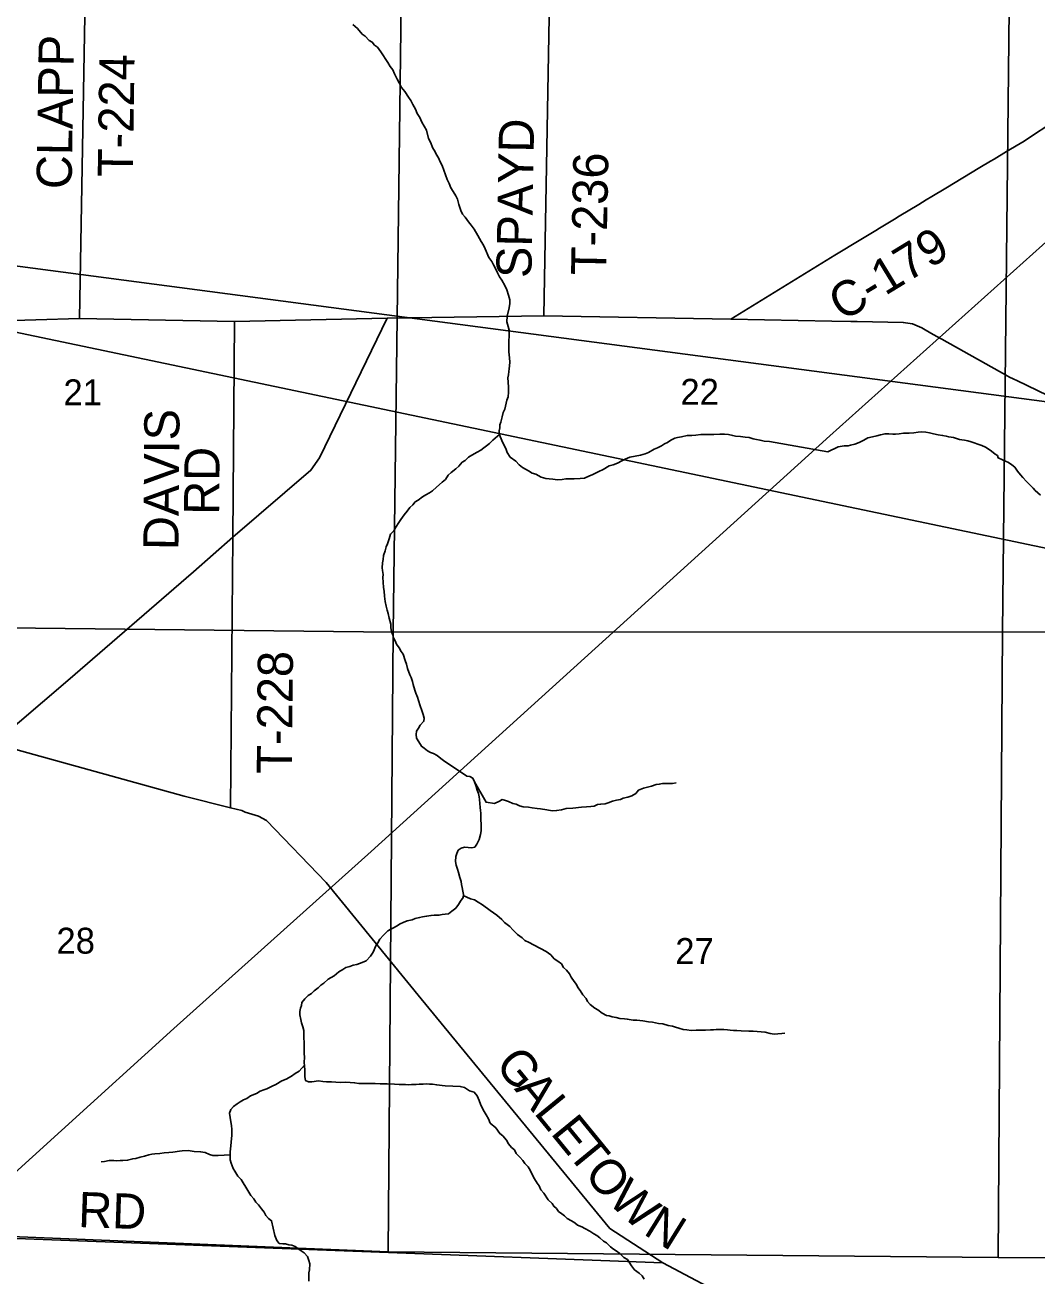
# Model space of a CAD drawing. Extents: x 0 to 34, y 0 to 22.
# Drawn here: x 4.9 to 6.537, y 15.401 to 17.423 of the extents above; entities that cross this region are included whole.
import ezdxf

# ---------------------------------------------------------------- set-up
doc = ezdxf.new("R2010")
doc.units = 0
for name, color, linetype in [('GM_X_County_Road', 7, 'Continuous'), ('GM_X_County_Road_Text', 7, 'Continuous'), ('GM_X_Minor_River', 7, 'Continuous'), ('GM_X_Rail_Line', 7, 'Continuous'), ('GM_X_Section', 7, 'Continuous'), ('GM_X_Section_Text', 7, 'Continuous'), ('GM_X_Township_Road', 7, 'Continuous'), ('GM_X_Township_Road_Text', 7, 'Continuous'), ('SH_Data', 7, 'Continuous')]:
    doc.layers.add(name, color=color, linetype=linetype)

msp = doc.modelspace()

# ---------------------------------------------------------------- linework, layer by layer
at = {"layer": 'GM_X_County_Road'}
for p, q in [((6.5219, 17.2393), (6.5642, 17.2669)), ((6.4445, 17.1926), (6.4617, 17.2029)), ((5.4858, 16.949), (5.7395, 16.953)), ((5.7395, 16.953), (6.0419, 16.9474)), ((6.0419, 16.9474), (6.2053, 16.9445)), ((6.2053, 16.9445), (6.2359, 16.9439)), ((6.2359, 16.9439), (6.2461, 16.9437)), ((6.3832, 16.9151), (6.4899, 16.8555))]:
    msp.add_line(p, q, dxfattribs=at)
for points in [[(6.4875, 17.2184), (6.516, 17.2354), (6.5219, 17.2393)], [(6.4617, 17.2029), (6.4677, 17.2065), (6.4875, 17.2184)], [(6.3669, 17.146), (6.3894, 17.1595), (6.4445, 17.1926)], [(6.3143, 17.1142), (6.3459, 17.1332), (6.3575, 17.1403), (6.3669, 17.146)], [(6.2901, 17.0995), (6.3067, 17.1095), (6.3143, 17.1142)], [(6.2127, 17.0527), (6.2496, 17.075), (6.2789, 17.0927), (6.2814, 17.0943)], [(6.2814, 17.0943), (6.2823, 17.0948), (6.2901, 17.0995)], [(6.0419, 16.9474), (6.2102, 17.0511), (6.2127, 17.0527)], [(3.4818, 16.701), (3.5794, 16.6905), (3.7487, 16.6707), (3.8927, 16.6551), (3.9667, 16.6771), (4.2269, 16.7584), (4.486, 16.8389), (4.7465, 16.9172), (4.8464, 16.9445), (4.9885, 16.9486), (5.2393, 16.9438), (5.4858, 16.949)], [(5.2364, 16.5952), (5.3627, 16.7033), (5.3766, 16.7236), (5.4858, 16.949)], [(6.2461, 16.9437), (6.3206, 16.9424), (6.3282, 16.9411), (6.3357, 16.9399), (6.3505, 16.9333), (6.3561, 16.9302)], [(6.3561, 16.9302), (6.3689, 16.923), (6.3832, 16.9151)], [(6.4899, 16.8555), (6.4917, 16.8545), (6.4994, 16.8506)], [(6.4994, 16.8506), (6.5042, 16.8482), (6.6203, 16.7926), (6.6936, 16.7596), (6.76, 16.7284), (6.7817, 16.7198), (6.7916, 16.7158), (6.7987, 16.7128), (6.8, 16.7123), (6.8036, 16.7112)], [(3.9812, 15.4992), (4.2172, 15.704), (4.4759, 15.927), (4.8499, 16.2614), (4.9696, 16.3635), (5.1729, 16.5392), (5.2364, 16.5952)]]:
    msp.add_lwpolyline(points, dxfattribs=at)
at = {"layer": 'GM_X_Minor_River'}
for points in [[(5.4307, 17.4238), (5.4379, 17.4176), (5.4457, 17.4081), (5.4506, 17.405), (5.457, 17.3981), (5.4619, 17.3954), (5.4656, 17.3904), (5.4701, 17.3873), (5.4757, 17.38), (5.4791, 17.375), (5.4839, 17.3674), (5.4873, 17.3624), (5.491, 17.3563), (5.4951, 17.3506), (5.4981, 17.3441), (5.5022, 17.3357), (5.5055, 17.3296), (5.5092, 17.3223), (5.5148, 17.3158), (5.5204, 17.3067), (5.5241, 17.3009), (5.5275, 17.2948), (5.532, 17.2872), (5.5345, 17.2803), (5.5386, 17.2734)], [(5.5386, 17.2734), (5.542, 17.2658), (5.5461, 17.2597), (5.5494, 17.2532), (5.5527, 17.2399), (5.556, 17.2338), (5.5597, 17.2239), (5.563, 17.2193), (5.5653, 17.2143), (5.569, 17.2086), (5.5719, 17.2017), (5.5749, 17.196), (5.5779, 17.1884), (5.5804, 17.1811), (5.583, 17.1735), (5.5863, 17.167), (5.5889, 17.1598), (5.5926, 17.154), (5.5971, 17.1468), (5.5997, 17.1414), (5.6019, 17.1331), (5.6033, 17.1281), (5.6052, 17.1235), (5.6078, 17.1171), (5.6123, 17.1125), (5.6175, 17.1048), (5.622, 17.0998), (5.6268, 17.0933), (5.6328, 17.083), (5.638, 17.0731), (5.6417, 17.067), (5.6447, 17.0612), (5.6506, 17.0475), (5.6551, 17.041), (5.658, 17.0353), (5.6625, 17.0273), (5.6647, 17.0223), (5.6677, 17.0162), (5.6714, 17.0108), (5.6763, 17.0021), (5.6796, 16.9948), (5.6821, 16.9864), (5.6843, 16.9788), (5.6843, 16.9731), (5.6831, 16.9659), (5.6799, 16.9523), (5.6794, 16.9432), (5.6816, 16.9356), (5.6834, 16.9299), (5.6833, 16.9189), (5.6828, 16.9135), (5.6826, 16.8949), (5.6836, 16.8851), (5.6843, 16.8782), (5.6839, 16.8722), (5.6834, 16.8672), (5.683, 16.8627), (5.6822, 16.8574), (5.6814, 16.8528), (5.6823, 16.838), (5.6823, 16.8297), (5.6818, 16.8221), (5.6798, 16.8164), (5.6762, 16.802), (5.6735, 16.7967), (5.6719, 16.7895), (5.6699, 16.7812), (5.6684, 16.7767), (5.6683, 16.7721), (5.6671, 16.7668), (5.6674, 16.7615), (5.6704, 16.7539), (5.6726, 16.7485), (5.6756, 16.7428), (5.6782, 16.7367), (5.68, 16.7321), (5.6848, 16.7245), (5.6939, 16.7179), (5.6995, 16.7122), (5.7051, 16.7076), (5.7146, 16.7025), (5.7206, 16.6987), (5.7263, 16.6971), (5.7349, 16.6921), (5.7425, 16.6901), (5.7478, 16.6893), (5.7542, 16.6888), (5.7614, 16.688), (5.769, 16.6883), (5.7747, 16.6893), (5.7812, 16.6893), (5.7884, 16.6896), (5.7982, 16.6899), (5.8051, 16.6905), (5.8131, 16.6943), (5.8177, 16.6957), (5.8283, 16.7013), (5.8356, 16.7043), (5.8448, 16.7102), (5.8516, 16.7121), (5.8585, 16.715)], [(5.6672, 16.7605), (5.6644, 16.7585), (5.6571, 16.7521), (5.6517, 16.7465), (5.6467, 16.7427), (5.6422, 16.7397), (5.6376, 16.7356), (5.6318, 16.7323), (5.6231, 16.7278), (5.6173, 16.7244), (5.612, 16.7192), (5.6074, 16.7162), (5.602, 16.7098), (5.597, 16.7057), (5.5897, 16.6997), (5.5848, 16.6952), (5.5805, 16.6884), (5.5751, 16.6843), (5.5659, 16.676), (5.5594, 16.67), (5.5545, 16.6667), (5.5487, 16.6633), (5.543, 16.6603), (5.5361, 16.6551), (5.5315, 16.6521), (5.5277, 16.6472), (5.5227, 16.6431), (5.5185, 16.6374), (5.5135, 16.631), (5.5081, 16.6239), (5.5046, 16.6186), (5.5, 16.6114), (5.4969, 16.6054), (5.4915, 16.5998), (5.4891, 16.5926), (5.4864, 16.5842), (5.4844, 16.5793), (5.4825, 16.5733), (5.4801, 16.5657), (5.4793, 16.5589), (5.4784, 16.5536), (5.478, 16.5456), (5.4783, 16.5411), (5.4794, 16.535), (5.4789, 16.53), (5.4796, 16.5224), (5.4803, 16.5137), (5.481, 16.5076), (5.4816, 16.5), (5.4827, 16.4909), (5.4845, 16.4837), (5.4859, 16.4772), (5.4878, 16.4715), (5.4892, 16.4643), (5.4921, 16.4544), (5.492, 16.4483), (5.4931, 16.4426), (5.4949, 16.4369), (5.4964, 16.4323), (5.499, 16.4277), (5.5012, 16.4224), (5.5053, 16.4163), (5.5087, 16.4105), (5.512, 16.4059), (5.515, 16.396), (5.5172, 16.3896), (5.519, 16.3827), (5.5227, 16.3728), (5.5249, 16.3682), (5.5267, 16.3617), (5.5282, 16.3572), (5.5307, 16.348), (5.5326, 16.3427), (5.5348, 16.3366), (5.5366, 16.3313), (5.5395, 16.3225), (5.5421, 16.3149), (5.5443, 16.3084), (5.5458, 16.3023), (5.5453, 16.2974), (5.5396, 16.291), (5.5369, 16.2865), (5.5334, 16.2816), (5.5329, 16.2763), (5.5333, 16.2702), (5.537, 16.2644), (5.5414, 16.2572), (5.546, 16.2541), (5.5512, 16.2495), (5.5561, 16.2468), (5.561, 16.2452), (5.5667, 16.2421), (5.5727, 16.2371), (5.5772, 16.234), (5.5889, 16.2259), (5.6047, 16.2155), (5.6149, 16.2089), (5.6198, 16.2081), (5.6247, 16.2054), (5.6273, 16.1997)], [(5.8585, 16.715), (5.8653, 16.7184), (5.8707, 16.7213), (5.8787, 16.7247), (5.8958, 16.7279), (5.9034, 16.7301), (5.9084, 16.732), (5.9179, 16.7375), (5.9232, 16.7394), (5.9297, 16.7427), (5.9343, 16.7461), (5.9396, 16.7483), (5.9446, 16.7517), (5.9511, 16.755), (5.9557, 16.7565), (5.9621, 16.7576), (5.9713, 16.7594), (5.9785, 16.7593), (5.9853, 16.76), (5.9933, 16.761), (5.9993, 16.7613), (6.0066, 16.7609), (6.0141, 16.7612), (6.024, 16.7618), (6.0316, 16.7618), (6.038, 16.7609), (6.0448, 16.7593), (6.0494, 16.7585), (6.0573, 16.7577), (6.0649, 16.7568), (6.0714, 16.756), (6.0782, 16.754), (6.0835, 16.7529), (6.0891, 16.7517), (6.0956, 16.7504), (6.1043, 16.7496), (6.1989, 16.733)], [(6.1989, 16.733), (6.2153, 16.7414), (6.2252, 16.7426), (6.2317, 16.7426), (6.2354, 16.7441), (6.2426, 16.7457), (6.2495, 16.7484), (6.2567, 16.7522), (6.2635, 16.7557), (6.2711, 16.7576), (6.2779, 16.7588), (6.2839, 16.7607), (6.2912, 16.7623), (6.2976, 16.7623), (6.3041, 16.7619), (6.3082, 16.7616), (6.3139, 16.7624), (6.3211, 16.7632), (6.3302, 16.7632), (6.3378, 16.7636), (6.3447, 16.7648), (6.3507, 16.7652), (6.3572, 16.7649), (6.3633, 16.7638), (6.3694, 16.7623), (6.3769, 16.7608), (6.3842, 16.7597), (6.3902, 16.7586), (6.3944, 16.7571), (6.402, 16.756), (6.4066, 16.7545), (6.4115, 16.753), (6.4153, 16.7526), (6.4195, 16.7522), (6.4252, 16.7508), (6.4305, 16.7493), (6.4355, 16.7478), (6.4412, 16.7455), (6.448, 16.7433), (6.4537, 16.7406), (6.4579, 16.738), (6.4633, 16.7342), (6.4693, 16.7293), (6.4732, 16.7271), (6.4743, 16.7233), (6.4812, 16.7199), (6.4911, 16.7161), (6.4964, 16.7123), (6.501, 16.7082), (6.5055, 16.7018), (6.5101, 16.6961), (6.5143, 16.6915), (6.5201, 16.6851), (6.5258, 16.6791), (6.5307, 16.6745), (6.5342, 16.6707), (6.5426, 16.6632)], [(5.6273, 16.1997), (5.6302, 16.1921), (5.6317, 16.186), (5.6335, 16.1807), (5.635, 16.1753), (5.6353, 16.1708), (5.6356, 16.1643), (5.6363, 16.1582), (5.637, 16.1533), (5.6373, 16.1487), (5.6376, 16.1423), (5.6376, 16.137), (5.6379, 16.132), (5.6381, 16.1206), (5.6369, 16.1142), (5.6346, 16.1062), (5.6311, 16.0987), (5.6276, 16.0938), (5.6227, 16.0931), (5.6113, 16.094), (5.6056, 16.0921), (5.601, 16.0891), (5.5986, 16.0838), (5.5971, 16.0789), (5.5966, 16.0706), (5.5977, 16.0649), (5.5995, 16.0584), (5.6013, 16.0531), (5.6035, 16.0451), (5.6057, 16.0386), (5.6064, 16.0337), (5.6071, 16.0287), (5.6086, 16.0226), (5.6093, 16.0173), (5.6088, 16.0124), (5.6046, 16.0067), (5.6011, 16.0011), (5.5969, 15.9954), (5.5908, 15.9905), (5.5854, 15.9864), (5.5797, 15.9854), (5.5751, 15.985), (5.5698, 15.9839), (5.5619, 15.984), (5.5569, 15.9837), (5.5497, 15.9823), (5.5429, 15.9812), (5.5383, 15.9801), (5.5314, 15.9787), (5.5265, 15.9764), (5.5185, 15.9746), (5.5117, 15.972), (5.5071, 15.9698), (5.501, 15.9661), (5.4964, 15.9635), (5.4918, 15.9616), (5.4872, 15.9586), (5.4799, 15.9515), (5.4742, 15.9451), (5.4711, 15.9391), (5.4676, 15.9342), (5.4633, 15.9243), (5.4591, 15.9179), (5.4518, 15.91), (5.4457, 15.9074), (5.4369, 15.9045), (5.4308, 15.9031), (5.4255, 15.9008), (5.4194, 15.8994), (5.4141, 15.896), (5.4079, 15.8923), (5.4003, 15.8859), (5.3907, 15.8807), (5.3835, 15.8739), (5.3789, 15.871), (5.3743, 15.8665), (5.3681, 15.8616), (5.3635, 15.8575), (5.3582, 15.8541), (5.3528, 15.8488), (5.3482, 15.8428), (5.3474, 15.8379), (5.3458, 15.8334), (5.345, 15.8284), (5.3446, 15.8227), (5.3464, 15.8151), (5.3475, 15.8102), (5.3497, 15.8033), (5.3511, 15.7976), (5.351, 15.7915), (5.3513, 15.7851), (5.352, 15.7786), (5.3518, 15.7604), (5.3521, 15.7543), (5.3517, 15.7456), (5.3524, 15.7403), (5.3527, 15.7334), (5.3526, 15.7289), (5.3529, 15.7224), (5.354, 15.7167), (5.3589, 15.7144)], [(5.6273, 16.1997), (5.6459, 16.1665), (5.6595, 16.1648), (5.6675, 16.1681), (5.6721, 16.1708), (5.6774, 16.1696), (5.6823, 16.1676), (5.6895, 16.1645), (5.6944, 16.1633), (5.7, 16.161), (5.7057, 16.1594), (5.7148, 16.1585), (5.7205, 16.1577), (5.7284, 16.1565), (5.7338, 16.156), (5.744, 16.1544), (5.7531, 16.1528), (5.7599, 16.1531), (5.7679, 16.1545), (5.7755, 16.1564), (5.7861, 16.157), (5.8005, 16.1587), (5.8085, 16.159), (5.8153, 16.1597), (5.8207, 16.1604), (5.826, 16.1627), (5.8313, 16.1637), (5.8385, 16.164), (5.8435, 16.1655), (5.8503, 16.1685), (5.8568, 16.1699), (5.8633, 16.171), (5.8678, 16.1732), (5.8755, 16.175), (5.8819, 16.1769), (5.888, 16.1806), (5.8923, 16.1859), (5.9007, 16.1896), (5.9136, 16.1928), (5.9208, 16.195), (5.9261, 16.1957), (5.9311, 16.1968), (5.9421, 16.1967), (5.9474, 16.1967), (5.9535, 16.1977)], [(5.6091, 16.0156), (5.621, 16.0103), (5.6274, 16.0088), (5.633, 16.0049), (5.6402, 16.0006), (5.6526, 15.9914), (5.6635, 15.9841), (5.6714, 15.9772), (5.6759, 15.9722), (5.6845, 15.9656), (5.689, 15.9603), (5.6969, 15.953), (5.7041, 15.9472), (5.7089, 15.9433), (5.7157, 15.9399), (5.7229, 15.936), (5.7342, 15.9302), (5.7429, 15.9251), (5.7508, 15.9197), (5.756, 15.9136), (5.7621, 15.9098), (5.7677, 15.9051), (5.771, 15.8994), (5.7759, 15.8952), (5.7808, 15.8891), (5.7838, 15.8837), (5.7882, 15.8768), (5.792, 15.8718), (5.7946, 15.8673), (5.7979, 15.8623), (5.8024, 15.855), (5.8076, 15.8493), (5.8099, 15.8443), (5.8144, 15.8397), (5.8219, 15.8339), (5.8268, 15.8312), (5.8339, 15.8258), (5.8407, 15.822), (5.8453, 15.8212), (5.8498, 15.8196), (5.8566, 15.8184), (5.8623, 15.8172), (5.8699, 15.8163), (5.8744, 15.8159), (5.8839, 15.8143), (5.8899, 15.8142), (5.8994, 15.8134), (5.9085, 15.8118), (5.9149, 15.8109), (5.9248, 15.8089), (5.9316, 15.8081), (5.9407, 15.8057), (5.9475, 15.8045), (5.9524, 15.8029), (5.9577, 15.8014), (5.9649, 15.799), (5.9709, 15.7986), (5.9774, 15.7977), (5.9857, 15.798), (5.9914, 15.798), (6.0009, 15.7982), (6.0089, 15.7989), (6.0138, 15.7989), (6.0183, 15.7992), (6.0305, 15.7991), (6.0362, 15.7986), (6.0407, 15.7982), (6.0464, 15.7978), (6.0513, 15.7977), (6.0585, 15.7969), (6.071, 15.7967), (6.0779, 15.7963), (6.0843, 15.7962), (6.0972, 15.7946), (6.1055, 15.7929), (6.112, 15.7917), (6.1177, 15.7921), (6.1245, 15.7927), (6.1294, 15.7931)], [(5.3522, 15.7415), (5.3435, 15.732), (5.3374, 15.7283), (5.3313, 15.7238), (5.3225, 15.719), (5.3157, 15.7164), (5.3057, 15.71), (5.3, 15.7074), (5.2916, 15.7033), (5.2863, 15.7019), (5.2806, 15.6993), (5.2748, 15.6959), (5.2649, 15.6919), (5.2588, 15.6874), (5.2535, 15.6852), (5.2481, 15.6822), (5.2432, 15.6788), (5.2374, 15.6747), (5.2332, 15.6698), (5.2312, 15.6638), (5.2319, 15.6569), (5.234, 15.6432), (5.2347, 15.6383), (5.2346, 15.628), (5.2342, 15.6231), (5.2337, 15.617), (5.2329, 15.6113), (5.2325, 15.6064), (5.232, 15.6015), (5.2319, 15.5882), (5.2337, 15.5832), (5.2367, 15.5745), (5.2397, 15.5699), (5.2445, 15.5623), (5.2501, 15.5565), (5.2531, 15.5515), (5.2576, 15.5443), (5.2609, 15.5389), (5.2654, 15.5309), (5.2702, 15.5255), (5.2736, 15.5202), (5.2781, 15.5156), (5.283, 15.5095), (5.2871, 15.5041), (5.2897, 15.4984), (5.2942, 15.4938), (5.2991, 15.4899), (5.3041, 15.4659), (5.3074, 15.4583), (5.3115, 15.4533), (5.3172, 15.4529), (5.3218, 15.4529), (5.3271, 15.4509), (5.332, 15.4505), (5.3373, 15.4485), (5.3422, 15.4447), (5.3471, 15.4416), (5.3516, 15.4381), (5.3572, 15.432), (5.3594, 15.4259), (5.3608, 15.4202), (5.3604, 15.4107), (5.3595, 15.4058), (5.3594, 15.3925)], [(5.3589, 15.7144), (5.3642, 15.7147), (5.3748, 15.7161), (5.382, 15.7149), (5.3877, 15.7148), (5.3957, 15.7144), (5.4029, 15.7139), (5.4105, 15.7135), (5.4188, 15.7138), (5.426, 15.7133), (5.4332, 15.7132), (5.44, 15.712), (5.4586, 15.7118), (5.4666, 15.7121), (5.4745, 15.7116), (5.4802, 15.7116), (5.4859, 15.7111), (5.4981, 15.711), (5.5053, 15.7102), (5.5159, 15.7101), (5.5208, 15.7096), (5.5254, 15.71), (5.5329, 15.7103), (5.5379, 15.7106), (5.544, 15.7109), (5.5493, 15.7112), (5.5546, 15.7108), (5.5595, 15.7107), (5.5663, 15.7095), (5.575, 15.7087), (5.58, 15.7082), (5.5921, 15.7073), (5.6042, 15.7072), (5.611, 15.7052), (5.6193, 15.7002), (5.6265, 15.6979), (5.6317, 15.6921), (5.6347, 15.6845), (5.6369, 15.6784), (5.6413, 15.6692), (5.6462, 15.6612), (5.6499, 15.6547), (5.6525, 15.6479), (5.6615, 15.6402), (5.6682, 15.631), (5.6731, 15.6271), (5.6791, 15.6202), (5.6824, 15.6145), (5.6873, 15.6084), (5.6918, 15.6049), (5.6948, 15.5988), (5.7008, 15.5927), (5.7053, 15.5873), (5.7086, 15.5823), (5.7143, 15.577), (5.7172, 15.5716), (5.7206, 15.5647), (5.7243, 15.5579), (5.7284, 15.551), (5.7317, 15.5464), (5.7347, 15.5399), (5.7396, 15.5346), (5.7463, 15.5238), (5.753, 15.5181), (5.7556, 15.5135), (5.7601, 15.5097), (5.7631, 15.5051), (5.7684, 15.5012), (5.7729, 15.4981), (5.777, 15.4935), (5.7842, 15.4897), (5.7895, 15.4866), (5.794, 15.4827), (5.8008, 15.4804), (5.8057, 15.4773), (5.814, 15.473), (5.8204, 15.4688), (5.8253, 15.4664), (5.8302, 15.4626), (5.8358, 15.4572), (5.8407, 15.4545), (5.8474, 15.448), (5.852, 15.4441), (5.8565, 15.4411), (5.8625, 15.4372), (5.8689, 15.4307), (5.8745, 15.4272), (5.8812, 15.4169), (5.8861, 15.4104), (5.8936, 15.405), (5.8985, 15.4011), (5.9019, 15.3958)], [(5.232, 15.5966), (5.2126, 15.5956), (5.2043, 15.5957), (5.1986, 15.5973), (5.1914, 15.6004), (5.1843, 15.6016), (5.174, 15.6021), (5.1642, 15.6034), (5.1547, 15.6031), (5.1501, 15.6024), (5.1395, 15.601), (5.1326, 15.6003), (5.1254, 15.6), (5.1182, 15.5985), (5.1102, 15.5979), (5.1053, 15.5975), (5.1004, 15.5964), (5.0935, 15.5942), (5.0863, 15.5928), (5.0794, 15.5906), (5.0745, 15.5903), (5.0661, 15.5877), (5.0585, 15.5874), (5.054, 15.5875), (5.0483, 15.5871), (5.0437, 15.5876), (5.0362, 15.5873), (5.0286, 15.5858), (5.0236, 15.5855)]]:
    msp.add_lwpolyline(points, dxfattribs=at)
at = {"layer": 'GM_X_Rail_Line'}
msp.add_lwpolyline([(3.6815, 14.4919), (3.8612, 14.6519), (4.1651, 14.9197), (4.4686, 15.1913), (4.7768, 15.471), (5.1412, 15.8006), (5.4601, 16.0872), (6.2018, 16.7592), (6.7493, 17.2493), (7.0065, 17.4955), (7.1712, 17.6375), (7.3789, 17.8309), (7.4524, 17.8921)], dxfattribs=at)
at = {"layer": 'GM_X_Section'}
for points in [[(5.5087, 17.4571), (5.4956, 16.4418), (4.4826, 16.453), (4.4991, 17.4554)], [(6.4919, 17.4489), (6.481, 16.4419), (5.4956, 16.4418), (5.5087, 17.4571)], [(6.4919, 17.4489), (7.5107, 17.4428), (7.4967, 16.4401), (6.481, 16.4419)], [(5.4956, 16.4418), (5.4878, 15.4398), (4.4671, 15.4814), (4.4826, 16.453)], [(6.481, 16.4419), (6.4743, 15.4308), (5.4878, 15.4398), (5.4956, 16.4418)], [(6.481, 16.4419), (7.4967, 16.4401), (7.4854, 15.4301), (6.4743, 15.4308)]]:
    msp.add_lwpolyline(points, close=True, dxfattribs=at)
at = {"layer": 'GM_X_Township_Road'}
msp.add_line((4.9885, 16.9486), (5.0061, 17.9488), dxfattribs=at)
for points in [[(5.7395, 16.953), (5.7574, 17.9498), (5.7604, 18.1653), (5.7658, 18.4109), (5.766, 18.4209)], [(5.2324, 16.1576), (5.2364, 16.5952), (5.2393, 16.9438)], [(5.5412, 15.849), (5.3873, 16.0366), (5.2909, 16.1369), (5.2777, 16.144), (5.2615, 16.1488), (5.2562, 16.1504), (5.2509, 16.1531), (5.2324, 16.1576), (5.1579, 16.1763), (4.8499, 16.2614), (4.7668, 16.2912), (4.7336, 16.2989), (4.5333, 16.3094), (4.4196, 16.3955), (4.3211, 16.4799), (4.2769, 16.5627), (4.2296, 16.6459), (4.2272, 16.6847), (4.2269, 16.7584)], [(6.3593, 15.1489), (6.2776, 15.2141), (6.156, 15.3006), (6.0845, 15.3409), (5.9317, 15.422), (5.846, 15.4777), (5.5412, 15.849)], [(3.9812, 15.4992), (4.4706, 15.4769), (5.9317, 15.422)]]:
    msp.add_lwpolyline(points, dxfattribs=at)
at = {"layer": 'SH_Data'}
msp.add_lwpolyline([(3.5095, 17.2146), (9.8001, 15.8963), (9.8001, 16.3863)], close=True, dxfattribs=at)

# ---------------------------------------------------------------- texts
at = {"layer": 'GM_X_County_Road_Text'}
msp.add_text('C-179', height=0.05682, rotation=31.4252, dxfattribs=at).set_placement((6.2229, 16.943))
at = {"layer": 'GM_X_Section_Text'}
for s, p in [('21', (4.9624, 16.8084)), ('22', (5.9603, 16.8092)), ('28', (4.9511, 15.9218)), ('27', (5.952, 15.9051))]:
    msp.add_text(s, height=0.04186, rotation=0, dxfattribs=at).set_placement(p)
at = {"layer": 'GM_X_Township_Road_Text'}
for s, height, rotation, p in [('CLAPP', 0.05682, 89.1157, (4.9756, 17.1575)), ('T-224', 0.05682, 89.1579, (5.0746, 17.1769)), ('SPAYD', 0.05682, 88.9513, (5.7192, 17.0138)), ('T-236', 0.05682, 88.8773, (5.8401, 17.0181)), ('DAVIS', 0.05682, 89.5493, (5.1484, 16.5741)), ('RD', 0.05682, 89.5045, (5.2142, 16.6311)), ('T-228', 0.05682, 89.4386, (5.3318, 16.2124)), ('G', 0.0568, 309.2384, (5.6589, 15.7417)), ('A', 0.0568, 309.2373, (5.6905, 15.703)), ('L', 0.0568, 309.2383, (5.7221, 15.6643)), ('E', 0.0568, 309.2388, (5.749, 15.6313)), ('T', 0.0568, 309.2388, (5.7759, 15.5984)), ('O', 0.0568, 309.3969, (5.8029, 15.5654)), ('W', 0.0568, 317.7868, (5.8409, 15.5202)), ('RD', 0.05682, 358.0252, (4.9857, 15.4799)), ('N', 0.0568, 328.1353, (5.8986, 15.4692))]:
    msp.add_text(s, height=height, rotation=rotation, dxfattribs=at).set_placement(p)

doc.saveas('drawing.dxf')
